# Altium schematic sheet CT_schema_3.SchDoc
size 410 x 311 mm
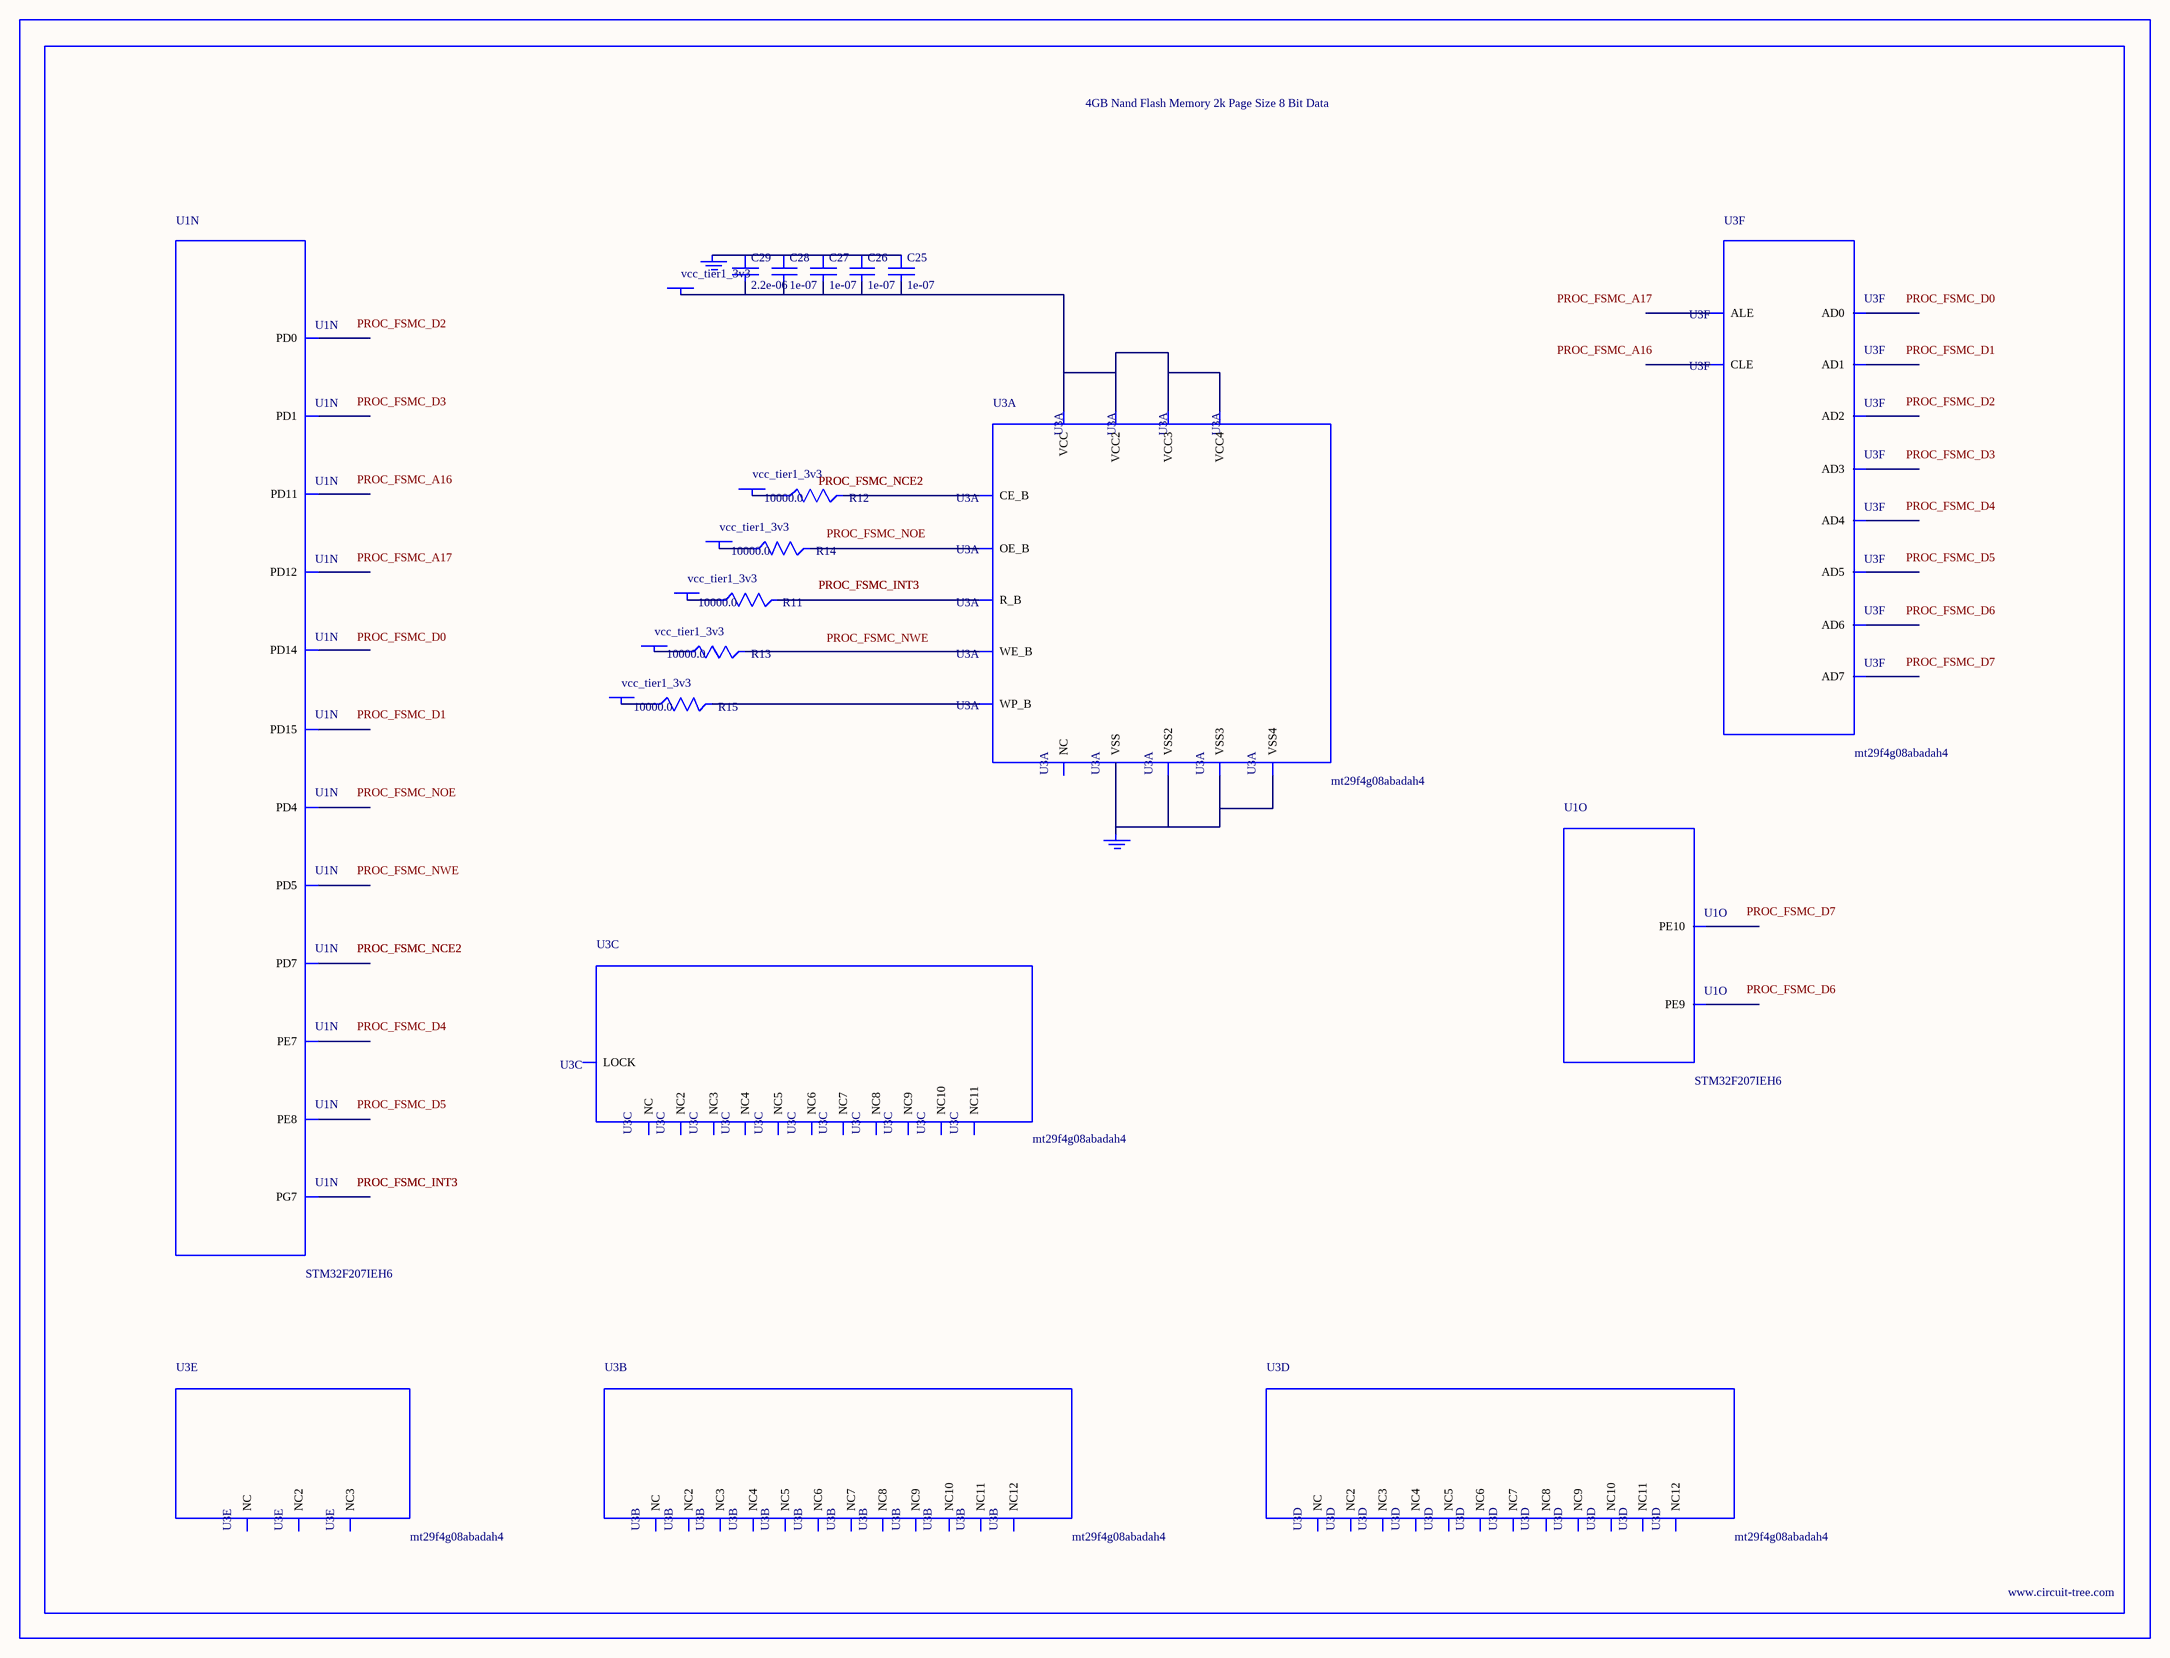
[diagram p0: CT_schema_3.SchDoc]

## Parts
BORDER2  (no value)
C25  1e-07  [C0402]
C26  1e-07  [C0402]
C27  1e-07  [C0402]
C28  1e-07  [C0402]
C29  2.2e-06  [C0603]
GND_INSTANCE_2_0  (no value)
GND_INSTANCE_2_1  (no value)
POWER_INSTANCE_2_0  vcc_tier1_3v3
POWER_INSTANCE_2_1  vcc_tier1_3v3
POWER_INSTANCE_2_2  vcc_tier1_3v3
POWER_INSTANCE_2_3  vcc_tier1_3v3
POWER_INSTANCE_2_4  vcc_tier1_3v3
POWER_INSTANCE_2_5  vcc_tier1_3v3
R11  10000.0  [R0603]
R12  10000.0  [R0603]
R13  10000.0  [R0603]
R14  10000.0  [R0603]
R15  10000.0  [R0603]
U1  STM32F207IEH6  [UFBGA176_25]  (parts N,O of 18)
U3  mt29f4g08abadah4  [VFBGA-63]  (parts A,B,C,D,E,F of 6)

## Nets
NetC25_1: C25.1 C26.1 C27.1 C28.1 C29.1 GND_INSTANCE_2_0.0(GND)
NetC25_2: C25.2 C26.2 C27.2 C28.2 C29.2 POWER_INSTANCE_2_0.0(PWR) U3.D3(VCC) U3.G4(VCC2) U3.H8(VCC3) U3.J6(VCC4)
NetGND_INSTANCE_2_1_0: GND_INSTANCE_2_1.0(GND) U3.C5(VSS) U3.F7(VSS2) U3.K3(VSS3) U3.K8(VSS4)
NetPOWER_INSTANCE_2_1_0: POWER_INSTANCE_2_1.0(PWR) R11.1
NetPOWER_INSTANCE_2_2_0: POWER_INSTANCE_2_2.0(PWR) R12.1
NetPOWER_INSTANCE_2_3_0: POWER_INSTANCE_2_3.0(PWR) R13.1
NetPOWER_INSTANCE_2_4_0: POWER_INSTANCE_2_4.0(PWR) R14.1
NetPOWER_INSTANCE_2_5_0: POWER_INSTANCE_2_5.0(PWR) R15.1
NetR11_2: R11.2 U3.C8(R_B)
NetR12_2: R12.2 U3.C6(CE_B)
NetR13_2: R13.2 U3.C7(WE_B)
NetR14_2: R14.2 U3.D4(OE_B)
NetR15_2: R15.2 U3.C3(WP_B)

Not connected (* = marked no-connect by the designer): U1 A11(PD7) B12(PD0) C11(PD5) C12(PD1) D10(PD4) J14(PG7) L14(PD15) M14(PD14) N13(PD12) N14(PD11) P8(PE8) P9(PE9) R8(PE7) R9(PE10); U3 A1(NC) A2(NC3) A9(NC4) A10(NC2) B1(NC5) B9(NC7) B10(NC6) C4(ALE) D5(CLE) D6(NC8) D7(NC9) D8(NC10) E3(NC11) E4(NC12) E5(NC) E6(NC2) E7(NC3) E8(NC4) F3(NC5) F4(NC6) F5(NC7) F6(NC8) F8(NC9) G3(NC) G5(LOCK) G6(NC10) G7(NC11) G8(NC) H3(NC2) H4(AD0) H5(NC3) H6(NC4) H7(NC5) J3(NC6) J4(AD1) J5(NC7) J7(AD5) J8(AD7) K4(AD2) K5(AD3) K6(AD4) K7(AD6) L1(NC8) L2(NC10) L9(NC11) L10(NC9) M1(NC12) M2(NC2) M9(NC3) M10(NC)

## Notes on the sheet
- Labels drawn without touching a wire or pin: PROC_FSMC_A16, PROC_FSMC_A17, PROC_FSMC_D0, PROC_FSMC_D1, PROC_FSMC_D2, PROC_FSMC_D3, PROC_FSMC_D4, PROC_FSMC_D5, PROC_FSMC_D6, PROC_FSMC_D7, PROC_FSMC_NOE, PROC_FSMC_NWE

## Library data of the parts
BORDER2 = BORDER_PAGE2
C25-C28 = C0402C104K3RACTU
C29 = C0603C225K8RACTU
GND_INSTANCE_2_0 GND_INSTANCE_2_1 = GND
POWER_INSTANCE_2_0-POWER_INSTANCE_2_5 = PWR
R11-R15 = RC0603JR-0710KL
